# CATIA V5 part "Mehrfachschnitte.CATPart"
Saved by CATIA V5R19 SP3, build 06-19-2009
Part number: Mehrfachschnitte
Bounding box of the stored display mesh (mm): x -10 to 250, y -40 to 190, z 0 to 100
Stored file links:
  C:\Tebisdaten\Mehrfachschnitte.CATPart
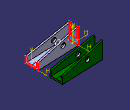
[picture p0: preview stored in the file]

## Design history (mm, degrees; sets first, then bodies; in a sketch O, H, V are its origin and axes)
AxisSystem1: origin (0, 0, 0), X (1, 0, 0), Y (0, 1, 0), Z (0, 0, 1)
Set1 "Geometrical Set.Defs Skizzen"
  Plane1: type Offset, RefPlane yz-plane, Offset 250
  Plane2: type Offset, RefPlane yz-plane, Offset -10
  Sketch1 "Skizze m - Schnitt 1" on Plane2, origin (-10, 0, 0), H (0, 1, 0), V (0, 0, 1)
    point P1 (-30, 100)
    line L1 (-30, 100) -> (-20, 100)
    point P2 (-20, 100)
    line L2 (-20, 100) -> (-20, 30)
    point P3 (-20, 30)
    line L3 (-20, 30) -> (0, 30)
    point P4 (0, 30)
    line L4 (-30, 100) -> (-30, 0)
    point P5 (-30, 0)
    line L5 (-30, 0) -> (0, 0)
    point P6 (0, 0)
    point P7 (30, 0)
    line L6 (30, 0) -> (0, 0)
    point P8 (30, 100)
    line L7 (30, 100) -> (30, 0)
    point P9 (20, 100)
    line L8 (30, 100) -> (20, 100)
    point P10 (20, 30)
    line L9 (20, 100) -> (20, 30)
    point P11 (0, 30)
    line L10 (20, 30) -> (0, 30)
    horizontal: L1 H, L3 H, L5 H
    vertical: L2 V, L4 V
    coincidence: P4 V, P5 H
    symmetry: O P6 V, P5 P7 V, L5 L6 V, P1 P8 V, L4 L7 V, P2 P9 V, L1 L8 V, P3 P10 V, L2 L9 V, P4 P11 V, L3 L10 V
  Sketch2 "Skizze m - Schnitt 2" on Plane1, origin (250, 0, 0), H (0, 1, 0), V (0, 0, 1)
    point P1 (-30, 40)
    line L1 (-30, 40) -> (-30, 10)
    point P2 (-30, 10)
    line L2 (-30, 10) -> (0, 10)
    point P3 (0, 10)
    line L3 (-30, 40) -> (-40, 40)
    point P4 (-40, 40)
    line L4 (-40, 40) -> (-40, 0)
    point P5 (-40, 0)
    line L5 (-40, 0) -> (0, 0)
    point P6 (0, 0)
    point P7 (40, 0)
    line L6 (40, 0) -> (0, 0)
    point P8 (40, 40)
    line L7 (40, 40) -> (40, 0)
    point P9 (30, 40)
    line L8 (30, 40) -> (40, 40)
    point P10 (30, 10)
    line L9 (30, 40) -> (30, 10)
    point P11 (0, 10)
    line L10 (30, 10) -> (0, 10)
    vertical: L1 V, L4 V
    coincidence: P3 V, P5 H
    horizontal: L2 H, L3 H, L5 H
    symmetry: O P6 V, P5 P7 V, L5 L6 V, P4 P8 V, L4 L7 V, P1 P9 V, L3 L8 V, P2 P10 V, L1 L9 V, P3 P11 V, L2 L10 V
  Plane3: type Offset, RefPlane zx-plane, Offset 0
  Sketch3 "Sketch.Loch" on Plane3, origin (0, 0, 0), H (-1, 0, 0), V (0, 0, 1)
    circle A1 centre (-90, 50) radius 14.1421
Body1 (main body)
Body2 "Partdesign"
  Loft1: solid, Sections (Sketch1; Sketch2)
  Pocket1: profile Sketch3, direction (0, -1, 0), through (limit type 3), opposite side through (limit type 3)
Body3 "G. Shape Design"
  Set2 "G. Shape Design"
    Loft2: Sections (Sketch1; Sketch2)
  CloseSurface1: CloseElement Loft2
  Pocket2: profile Sketch3, direction (0, 1, 0), through (limit type 3), opposite side through (limit type 3)
  Translate1: ToTransfor Pocket2, Direction (0, 1, 0), Length 150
